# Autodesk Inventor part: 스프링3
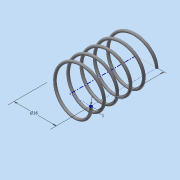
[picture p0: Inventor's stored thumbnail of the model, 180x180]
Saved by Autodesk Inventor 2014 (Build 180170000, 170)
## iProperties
Created: 2015-06
Part Number: 스프링3
Material: 강철, 연강
Document SubType Name: Modeling
Designer: MYHOME
Density: 1 g/cm^3
Appearance: 강철
Author: MYHOME
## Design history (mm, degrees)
sketch "스케치1"
  geometry: L1 (0, 0)-(8, 0); L2 (8, 0)-(8, 21.5); L3 (8, 21.5)-(0, 21.5); L4 (0, 21.5)-(0, 0); C1 r 0.5 at (8, 0)
  constraints: 8 end point, 2 parallel, 1 centre point, 1 coincident, 1 horizontal, 1 perpendicular
  dimensions: "d0" = 16 diameter of L2 L4; "d1" = 21.5 distance of L1.end L2.end (derived); "d2" = 1 diameter of C1
feature "코일1" sketch "스케치1" pitch "d3" = 10; turns "d5" = 5; dims "d4" = 21.5 (= d1), "d6" = 0, angle "d7" = 90 deg, angle "d8" = 90 deg, "d9" = 0, "d10" = 0
node "작업 평면1"
sketch "스케치2"
  geometry: L1 (-8.5, 0)-(-7.5, 0) reference; 1 further point
  constraints: 1 horizontal alignment
extrude "돌출1" cut sketch "스케치2" stored distance "d12" = 10; taper "d13" = 0 deg
node "작업 평면2"
sketch "스케치3"
  geometry: L1 (8.5, 0)-(7.5, 0) reference; 1 further point
  constraints: 1 horizontal alignment
extrude "돌출2" cut sketch "스케치3" stored distance "d15" = 10; taper "d16" = 0 deg
node "솔리드1"
node "절단 모서리 투영1"
node "절단 모서리 투영2"
other parameters: "d11" = 0, "d14" = -21.5 (= -d1)
